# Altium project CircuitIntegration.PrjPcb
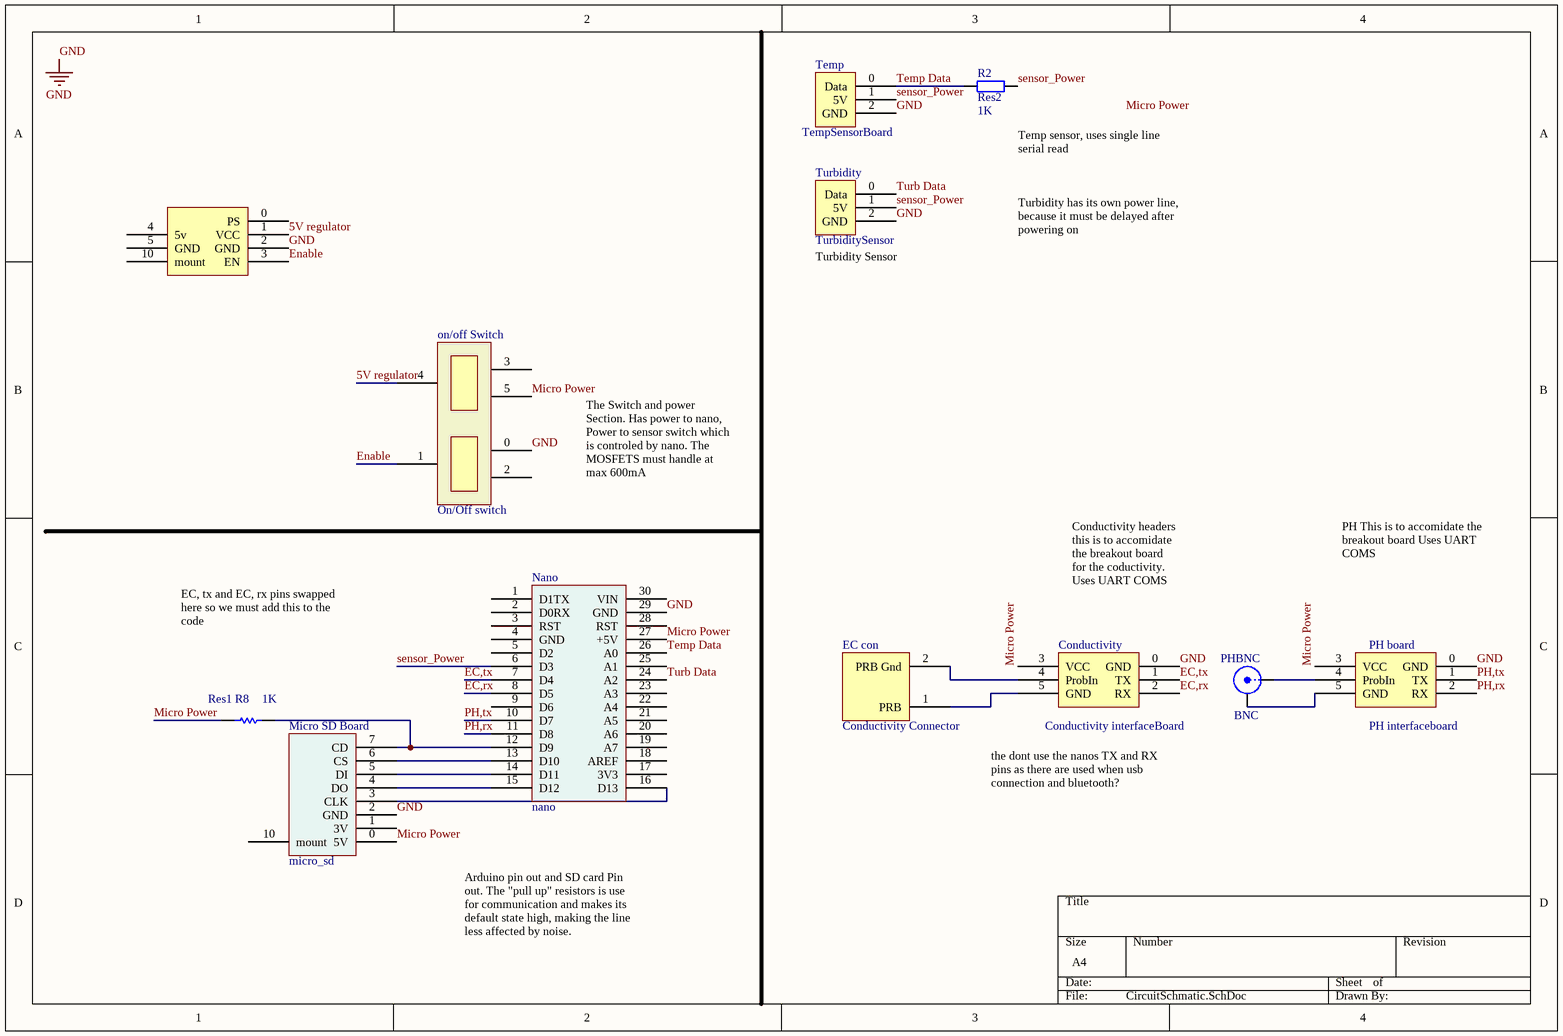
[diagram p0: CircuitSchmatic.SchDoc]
1 sheet, 12 parts. Net scope: global (net labels, ports and power ports of the same name join across sheets).
Board file: PCBDesign.PcbDoc

## Sheet CircuitSchmatic.SchDoc
size A4

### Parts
Charger  Charger/Booster  [CHARGER/BOOSTER]  (value not drawn)
Conductivity  Conductivity interfaceBoard  [CONDUCTIVITY INTERFACE BOARD - duplicate]
EC_con  Conductivity Connector  [Conductivity Connector (no BNC)]
Micro_SD_Board  micro_sd  [Micro SD]
Nano  nano  [NANO]
on/off_Switch  On/Off switch  [On/Off Switch]
PH_board  PH interfaceboard  [PH INTERFACE BOARD]
PHBNC  BNC  [BNC_RA CON]
R2  Res2  value 1K  [AXIAL-0.3]
R8  Res1  value 1K  [AXIAL-0.3]
Temp  TempSensorBoard  [TEMP HEADER]
Turbidity  TurbiditySensor  [TURBIDTY HEADER]

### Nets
GND: Charger.2(GND) Conductivity.0(GND) Micro_SD_Board.2(GND) Nano.29(GND) on/off_Switch.0 PH_board.0(GND) Temp.2(GND) Turbidity.2(GND)
5V regulator: Charger.1(VCC) on/off_Switch.4
EC,rx: Conductivity.2(RX) Nano.8(D5)
EC,tx: Conductivity.1(TX) Nano.7(D4)
Enable: Charger.3(EN) on/off_Switch.1
Micro Power: Conductivity.3(VCC) Micro_SD_Board.0(5V) Nano.27(+5V) on/off_Switch.5 PH_board.3(VCC) R8.1
PH,rx: Nano.11(D8) PH_board.2(RX)
PH,tx: Nano.10(D7) PH_board.1(TX)
sensor_Power: Nano.6(D3) R2.2 Temp.1(5V) Turbidity.1(5V)
Temp Data: Nano.26(A0) R2.1 Temp.0(Data)
Turb Data: Nano.24(A2) Turbidity.0(Data)
NetConductivity_4: Conductivity.4(ProbIn) EC_con.2(PRB_Gnd)
NetConductivity_5: Conductivity.5(GND) EC_con.1(PRB)
NetMicro_SD_Board_3: Micro_SD_Board.3(CLK) Nano.16(D13)
NetMicro_SD_Board_4: Micro_SD_Board.4(DO) Nano.15(D12)
NetMicro_SD_Board_5: Micro_SD_Board.5(DI) Nano.14(D11)
NetMicro_SD_Board_6: Micro_SD_Board.6(CS) Nano.13(D10)
NetMicro_SD_Board_7: Micro_SD_Board.7(CD) Nano.12(D9) R8.2
NetPH_board_4: PH_board.4(ProbIn) PHBNC.1(X)
NetPH_board_5: PH_board.5(GND) PHBNC.2(Y)

Not connected (* = marked no-connect by the designer): Charger 0(PS) 4(5v) 5(GND) 10(mount); Micro_SD_Board 1(3V) 10(mount); Nano 1(D1TX) 2(D0RX) 3(RST) 4(GND) 5(D2) 9(D6) 17(3V3) 18(AREF) 19(A7) 20(A6) 21(A5) 22(A4) 23(A3) 25(A1) 28(RST) 30(VIN); on/off_Switch 2 3

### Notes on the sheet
- (near R2) Temp sensor, uses single line serial read
- Turbidity has its own power line, because it must be delayed after powering on
- (near Turbidity) Turbidity Sensor
- The Switch and power Section. Has power to nano, Power to sensor switch which is controled by nano. The MOSFETS must handle at max 600mA
- PH This is to accomidate the breakout board Uses UART COMS
- EC, tx and EC, rx pins swapped here so we must add this to the code
- Conductivity headers	this is to accomidate the breakout board for the coductivity. Uses UART COMS
- the dont use the nanos TX and RX pins as there are used when usb connection and bluetooth?
- Arduino pin out and SD card Pin out. The "pull up" resistors is use for communication and makes its default state high, making the line less affected by noise.
- Labels drawn without touching a wire or pin: Micro Power

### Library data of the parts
PHBNC = BNC: BNC Elbow Connector
R2 = Res2: Resistor
R8 = Res1: Resistor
